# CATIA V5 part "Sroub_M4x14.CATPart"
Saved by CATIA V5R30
Part number: Sroub_M4x14
Definition: 2025_05_12_09_08_15_0928
Nomenclature: 2025_05_12_09_08_15_0928
Source: Unknown
Description: PART--DESC
Bounding box of the stored display mesh (mm): x 5.5 to 12.5, y 30.01 to 36.99, z -5 to 9
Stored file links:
  E:\Bakalarka\Model\Forma_v7\Sroub_M4x14.CATPart
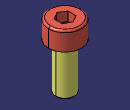
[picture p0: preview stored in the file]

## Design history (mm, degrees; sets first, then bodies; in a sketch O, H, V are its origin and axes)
Body1 "E2716_16B_NAUO5#E1200_4x10;Importiert1" (main body)
  Solid1: solid without history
